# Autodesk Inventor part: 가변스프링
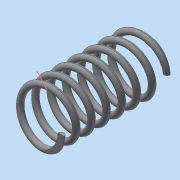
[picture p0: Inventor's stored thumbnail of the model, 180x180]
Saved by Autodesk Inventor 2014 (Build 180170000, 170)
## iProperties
Created: 2022-08
Part Number: 가변스프링
Material: 일반
Document SubType Name: Sheet Metal
Designer: dg
Density: 1 g/cm^3
Sheet Metal Rule: Default_mm
Appearance: 기본값
Mass: 8.72822 g
Surface Area: 88.3602 cm^2
Volume: 8.72822 cm^3
Author: dg
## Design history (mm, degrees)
sketch "스케치1"
  geometry: L1 (16, 0)-(0, 0); L2 (0, 0)-(0, 64); L3 (0, 64)-(16, 64); C1 r 2 at (16, 0)
  constraints: 6 end point, 1 centre point, 1 coincident, 1 horizontal, 1 parallel, 1 perpendicular, 1 vertical alignment
  dimensions: "d0" = 4 diameter of C1; "d1" = 32 diameter of L1.start L2; "d2" = 64 distance of L1.end L2.end (derived)
feature "코일1" pitch "d3" = 10; turns "d5" = 7; dims "d4" = 64 (= d2), "d6" = 0, angle "d7" = 90 deg, angle "d8" = 90 deg, "d9" = 0, "d10" = 0
node "작업 평면1"
feature "분할1"
feature "분할2"
node "솔리드1"
other parameters: "SeamGap" = 0.01, "d11" = 90 deg
